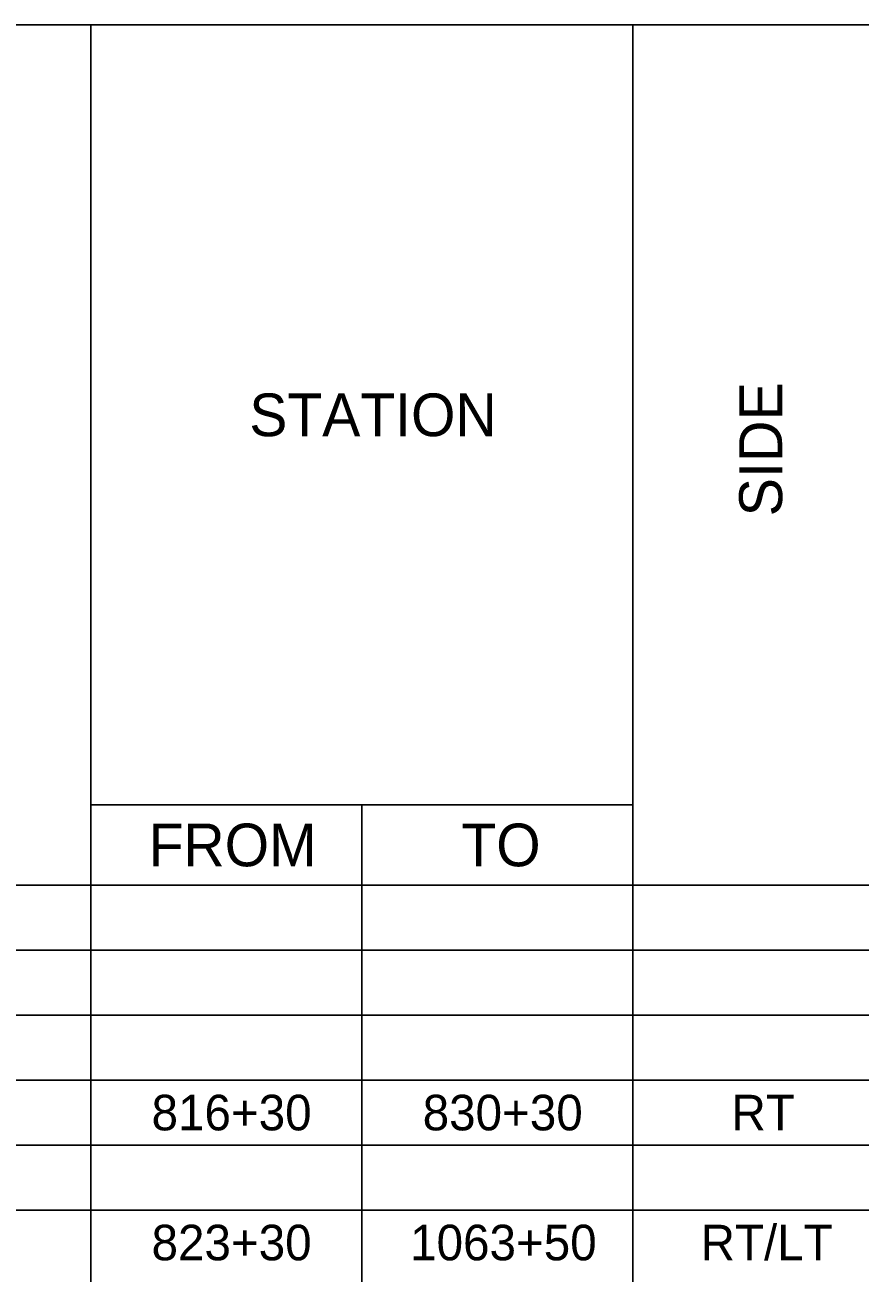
# Model space of a CAD drawing. Extents: x 91011267 to 91022583, y 37007614 to 37014266.
# Drawn here: x 91011467.7 to 91011644.4, y 37009680.8 to 37009944.6 of the extents above; entities that cross this region are included whole.
import ezdxf

# ---------------------------------------------------------------- set-up
doc = ezdxf.new("R2010")
doc.units = 0
doc.layers.add('SC_Scratch2', color=7, linetype='Continuous')
doc.layers.add('SH_Data', color=7, linetype='Continuous')

msp = doc.modelspace()

# ---------------------------------------------------------------- linework, layer by layer
at = {"layer": 'SC_Scratch2'}
msp.add_lwpolyline([(91011277.35, 37009944.63), (91012802.35, 37009944.63), (91012802.35, 37008894.63), (91011277.35, 37008894.63)], close=True, dxfattribs=at)
at = {"layer": 'SH_Data'}
for p, q in [((91011277.35, 37009944.63), (91011596.32, 37009944.63)), ((91011481.65, 37009944.63), (91011481.65, 37009853.7)), ((91011596.32, 37009944.63), (91011650.36, 37009944.63)), ((91011596.32, 37009944.63), (91011596.32, 37009853.7)), ((91011481.65, 37009853.7), (91011481.65, 37009779.77)), ((91011596.32, 37009853.7), (91011596.32, 37009779.77)), ((91011481.65, 37009779.77), (91011596.32, 37009779.77)), ((91011481.65, 37009779.77), (91011481.65, 37009762.76)), ((91011538.99, 37009779.77), (91011538.99, 37009762.76)), ((91011596.32, 37009779.77), (91011596.32, 37009762.76)), ((91011277.35, 37009762.76), (91011596.32, 37009762.76)), ((91011481.65, 37009762.76), (91011481.65, 37009652.86)), ((91011538.99, 37009762.76), (91011538.99, 37009652.86)), ((91011596.32, 37009762.76), (91011650.36, 37009762.76)), ((91011596.32, 37009762.76), (91011596.32, 37009652.86)), ((91011277.35, 37009749.02), (91011596.32, 37009749.02)), ((91011596.32, 37009749.02), (91011650.36, 37009749.02)), ((91011277.35, 37009735.29), (91011596.32, 37009735.29)), ((91011596.32, 37009735.29), (91011650.36, 37009735.29)), ((91011277.35, 37009721.55), (91011596.32, 37009721.55)), ((91011596.32, 37009721.55), (91011650.36, 37009721.55)), ((91011277.35, 37009707.81), (91011596.32, 37009707.81)), ((91011596.32, 37009707.81), (91011650.36, 37009707.81)), ((91011277.35, 37009694.07), (91011596.32, 37009694.07)), ((91011596.32, 37009694.07), (91011650.36, 37009694.07))]:
    msp.add_line(p, q, dxfattribs=at)

# ---------------------------------------------------------------- texts
msp.add_text('SIDE', height=9.095, rotation=90, dxfattribs=at).set_placement((91011627.89, 37009840.73))
for s, height, p in [('STATION', 9.028, (91011515.19, 37009857.69)), ('FROM', 9.028, (91011493.89, 37009766.75)), ('TO', 9.028, (91011560.04, 37009766.75)), ('816+30', 7.523, (91011494.52, 37009710.92)), ('830+30', 7.523, (91011551.86, 37009710.92)), ('RT', 7.523, (91011617.17, 37009710.92)), ('RT/LT', 7.523, (91011610.64, 37009683.44)), ('823+30', 7.523, (91011494.52, 37009683.44)), ('1063+50', 7.523, (91011549.21, 37009683.44))]:
    msp.add_text(s, height=height, dxfattribs=at).set_placement(p)

doc.saveas('drawing.dxf')
